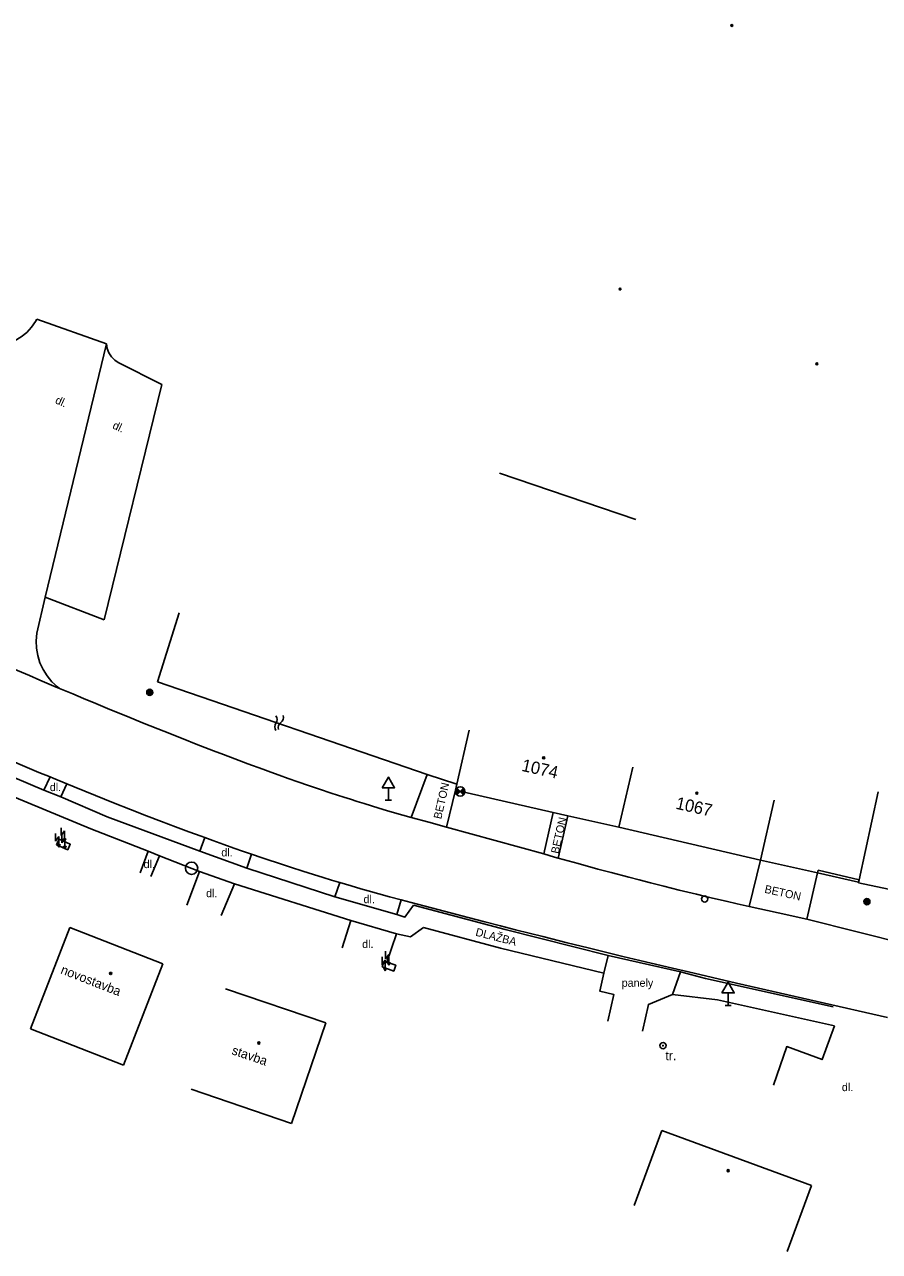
# Model space of a CAD drawing. Extents: x -540235 to -537963, y -1184915 to -1183660.
# Drawn here: x -538119.7 to -538050.3, y -1183997 to -1183897.3 of the extents above; entities that cross this region are included whole.
import ezdxf

# ---------------------------------------------------------------- set-up
doc = ezdxf.new("R2010")
doc.units = 0
for name, color, linetype in [('Vrstva 10', 7, 'Continuous'), ('Vrstva 11', 7, 'Continuous'), ('Vrstva 17', 7, 'Continuous'), ('Vrstva 20', 7, 'Continuous'), ('Vrstva 24', 7, 'Continuous'), ('Vrstva 25', 7, 'Continuous'), ('Vrstva 27', 7, 'Continuous'), ('Vrstva 28', 7, 'Continuous'), ('Vrstva 34', 7, 'Continuous'), ('Vrstva 39', 7, 'Continuous'), ('Vrstva 40', 7, 'Continuous'), ('Vrstva 41', 7, 'Continuous'), ('Vrstva 42', 7, 'Continuous'), ('Vrstva 47', 7, 'Continuous'), ('Vrstva 5', 7, 'Continuous'), ('Vrstva 7', 7, 'Continuous'), ('Vrstva 8', 7, 'Continuous')]:
    doc.layers.add(name, color=color, linetype=linetype)

msp = doc.modelspace()

# ---------------------------------------------------------------- linework, layer by layer
at = {"layer": 'Vrstva 10'}
for p, q in [((-538094.79, -1183959.736), (-538095.751, -1183959.417)), ((-538112.464, -1183960.529), (-538111.086, -1183961.074)), ((-538081.475, -1183963.59), (-538085.42, -1183962.5)), ((-538091.802, -1183967.666), (-538090.927, -1183967.911)), ((-538082.301, -1183970.194), (-538081.028, -1183970.522)), ((-538037.3, -1183974.7), (-538056.16, -1183969.97)), ((-538072.413, -1183972.672), (-538071.097, -1183972.991)), ((-538072.3, -1183972.91), (-538072.64, -1183974.37)), ((-538066.42, -1183974.26), (-538067.06, -1183976.08)), ((-538061.87, -1183975.16), (-538055.33, -1183976.652)), ((-538055.33, -1183976.652), (-538049.607, -1183977.953))]:
    msp.add_line(p, q, dxfattribs=at)
for points in [[(-538112.781, -1183952.939), (-538113.923, -1183952.469), (-538114.92, -1183952.054), (-538115.792, -1183951.69), (-538116.856, -1183951.241), (-538117.316, -1183951.047), (-538118.457, -1183950.561), (-538119.311, -1183950.194), (-538120.592, -1183949.64), (-538121.87, -1183949.08)], [(-538104.353, -1183956.303), (-538105.763, -1183955.757), (-538106.819, -1183955.342), (-538108.401, -1183954.714), (-538109.98, -1183954.08), (-538111.475, -1183953.474), (-538112.781, -1183952.939)], [(-538095.751, -1183959.417), (-538096.65, -1183959.113), (-538097.492, -1183958.822), (-538098.28, -1183958.547), (-538099.017, -1183958.285), (-538099.708, -1183958.037), (-538100.354, -1183957.803), (-538101.565, -1183957.357), (-538102.622, -1183956.962), (-538103.546, -1183956.612), (-538104.353, -1183956.303)], [(-538120.933, -1183957.045), (-538120.06, -1183957.413), (-538118.532, -1183958.053), (-538117.635, -1183958.425), (-538117.384, -1183958.529), (-538116.266, -1183958.988), (-538115.659, -1183959.237), (-538113.93, -1183959.94), (-538112.464, -1183960.529)], [(-538085.42, -1183962.5), (-538086.855, -1183962.105), (-538088.29, -1183961.71), (-538088.982, -1183961.517), (-538089.651, -1183961.326), (-538090.299, -1183961.137), (-538090.925, -1183960.951), (-538091.531, -1183960.769), (-538092.117, -1183960.589), (-538092.684, -1183960.413), (-538093.233, -1183960.24), (-538093.763, -1183960.07), (-538094.79, -1183959.736)], [(-538111.086, -1183961.074), (-538109.793, -1183961.578), (-538108.578, -1183962.045), (-538107.436, -1183962.477), (-538106.365, -1183962.877), (-538105.359, -1183963.247), (-538105.068, -1183963.353), (-538104.414, -1183963.59), (-538103.527, -1183963.908), (-538102.694, -1183964.202), (-538101.912, -1183964.475)], [(-538074.738, -1183965.466), (-538076.35, -1183965.02), (-538076.645, -1183964.936), (-538077.087, -1183964.807), (-538077.53, -1183964.68), (-538081.475, -1183963.59)], [(-538101.912, -1183964.475), (-538101.26, -1183964.7), (-538101.178, -1183964.728), (-538100.49, -1183964.963)], [(-538100.49, -1183964.963), (-538099.843, -1183965.18), (-538099.236, -1183965.382), (-538098.097, -1183965.755), (-538097.097, -1183966.076), (-538096.222, -1183966.352), (-538095.454, -1183966.589), (-538094.782, -1183966.794), (-538094.193, -1183966.971), (-538094.082, -1183967.004), (-538093.16, -1183967.276), (-538092.385, -1183967.501), (-538091.802, -1183967.666)], [(-538065.132, -1183967.947), (-538066.54, -1183967.605), (-538067.771, -1183967.299), (-538068.846, -1183967.027), (-538069.787, -1183966.785), (-538070.609, -1183966.572), (-538072.047, -1183966.193), (-538073.124, -1183965.904), (-538074.738, -1183965.466)], [(-538090.927, -1183967.911), (-538090.05, -1183968.15), (-538089.098, -1183968.406), (-538088.295, -1183968.621), (-538086.65, -1183969.059), (-538085.107, -1183969.465), (-538083.659, -1183969.843), (-538082.301, -1183970.194)], [(-538056.16, -1183969.97), (-538058.495, -1183969.455), (-538060.83, -1183968.94), (-538061.806, -1183968.722), (-538062.721, -1183968.514), (-538063.578, -1183968.315), (-538064.38, -1183968.127), (-538065.132, -1183967.947)], [(-538081.028, -1183970.522), (-538079.834, -1183970.826), (-538077.594, -1183971.392), (-538075.633, -1183971.881), (-538073.916, -1183972.305), (-538072.413, -1183972.672)], [(-538071.097, -1183972.991), (-538068.793, -1183973.544), (-538067.064, -1183973.954), (-538065.766, -1183974.258), (-538063.819, -1183974.712), (-538061.87, -1183975.16)], [(-538072.64, -1183974.37), (-538072.97, -1183975.83), (-538071.83, -1183976.1), (-538072.32, -1183978.268)], [(-538067.06, -1183976.08), (-538069.02, -1183976.9), (-538069.508, -1183979.057)]]:
    msp.add_lwpolyline(points, dxfattribs=at)
at = {"layer": 'Vrstva 11'}
for p, q in [((-538113.05, -1183923.26), (-538118.71, -1183921.25)), ((-538118.02, -1183943.82), (-538113.05, -1183923.26)), ((-538108.56, -1183926.57), (-538112.09, -1183924.78)), ((-538113.23, -1183945.67), (-538108.56, -1183926.57)), ((-538118.7, -1183946.76), (-538118.02, -1183943.82)), ((-538118.02, -1183943.82), (-538113.23, -1183945.67)), ((-538124.61, -1183956.73), (-538118.14, -1183959.51)), ((-538114.31, -1183962.64), (-538124.69, -1183958.34)), ((-538118.14, -1183959.51), (-538117.635, -1183958.425)), ((-538087, -1183958.23), (-538088.29, -1183961.71)), ((-538116.76, -1183960.05), (-538118.14, -1183959.51)), ((-538116.76, -1183960.05), (-538116.266, -1183958.988)), ((-538084.7, -1183959.51), (-538085.42, -1183962.5)), ((-538116.76, -1183960.05), (-538113, -1183961.67)), ((-538113, -1183961.67), (-538105.47, -1183964.46)), ((-538076.767, -1183961.304), (-538077.53, -1183964.68)), ((-538075.571, -1183961.574), (-538076.35, -1183965.02)), ((-538109.67, -1183964.45), (-538114.31, -1183962.64)), ((-538105.47, -1183964.46), (-538105.068, -1183963.353)), ((-538109.67, -1183964.45), (-538110.31, -1183966.2)), ((-538109.67, -1183964.45), (-538108.73, -1183964.83)), ((-538108.73, -1183964.83), (-538109.44, -1183966.51)), ((-538105.48, -1183966.11), (-538108.73, -1183964.83)), ((-538101.65, -1183965.83), (-538105.47, -1183964.46)), ((-538101.65, -1183965.83), (-538101.26, -1183964.7)), ((-538094.5, -1183968.16), (-538101.65, -1183965.83)), ((-538059.93, -1183965.17), (-538060.83, -1183968.94)), ((-538106.53, -1183968.84), (-538105.48, -1183966.11)), ((-538105.48, -1183966.11), (-538102.65, -1183967.1)), ((-538055.29, -1183966.2), (-538056.16, -1183969.97)), ((-538102.65, -1183967.1), (-538103.73, -1183969.68)), ((-538093.2, -1183970.08), (-538102.65, -1183967.1)), ((-538094.082, -1183967.004), (-538094.5, -1183968.16)), ((-538094.5, -1183968.16), (-538089.47, -1183969.6)), ((-538089.47, -1183969.6), (-538089.098, -1183968.406)), ((-538080.65, -1183970.8), (-538088.1, -1183968.83)), ((-538093.91, -1183972.31), (-538093.2, -1183970.08)), ((-538093.2, -1183970.08), (-538089.48, -1183971.16)), ((-538081.04, -1183972.32), (-538087.29, -1183970.64)), ((-538072.3, -1183972.91), (-538080.65, -1183970.8)), ((-538089.48, -1183971.16), (-538090.29, -1183973.54)), ((-538072.64, -1183974.37), (-538081.04, -1183972.32)), ((-538072.3, -1183972.91), (-538066.42, -1183974.26)), ((-538064.39, -1183974.78), (-538066.42, -1183974.26)), ((-538054.01, -1183977.1), (-538064.39, -1183974.78)), ((-538063.41, -1183976.53), (-538067.06, -1183976.08)), ((-538053.92, -1183978.64), (-538063.41, -1183976.53))]:
    msp.add_line(p, q, dxfattribs=at)
for points in [[(-538123.24, -1183923.34), (-538122.675, -1183923.427), (-538122.103, -1183923.435), (-538121.536, -1183923.363), (-538120.984, -1183923.213), (-538120.459, -1183922.987), (-538119.97, -1183922.69), (-538119.528, -1183922.328), (-538119.14, -1183921.908), (-538118.815, -1183921.438), (-538118.71, -1183921.25)], [(-538113.05, -1183923.26), (-538112.992, -1183923.637), (-538112.856, -1183923.994), (-538112.649, -1183924.315), (-538112.38, -1183924.586), (-538112.09, -1183924.78)], [(-538118.7, -1183946.76), (-538118.756, -1183947.367), (-538118.733, -1183947.975), (-538118.63, -1183948.576), (-538118.449, -1183949.158), (-538118.194, -1183949.711), (-538117.868, -1183950.226), (-538117.478, -1183950.694), (-538117.03, -1183951.107), (-538116.856, -1183951.241)], [(-538088.1, -1183968.83), (-538088.8, -1183969.81), (-538089.47, -1183969.6)], [(-538087.29, -1183970.64), (-538088.35, -1183971.41), (-538089.48, -1183971.16)], [(-538053.92, -1183978.64), (-538054.92, -1183981.38), (-538057.79, -1183980.32), (-538058.87, -1183983.44)]]:
    msp.add_lwpolyline(points, dxfattribs=at)
at = {"layer": 'Vrstva 17'}
for p, q in [((-538084.684, -1183959.621), (-538084.487, -1183959.423)), ((-538084.681, -1183959.547), (-538084.522, -1183959.388)), ((-538084.676, -1183959.683), (-538084.451, -1183959.459)), ((-538084.659, -1183959.737), (-538084.416, -1183959.494)), ((-538084.653, -1183959.448), (-538084.557, -1183959.353)), ((-538084.636, -1183959.785), (-538084.381, -1183959.529)), ((-538084.608, -1183959.827), (-538084.345, -1183959.565)), ((-538084.575, -1183959.865), (-538084.045, -1183959.335)), ((-538084.575, -1183959.335), (-538084.045, -1183959.865)), ((-538084.275, -1183959.635), (-538084.012, -1183959.373)), ((-538084.239, -1183959.671), (-538083.984, -1183959.415)), ((-538084.204, -1183959.706), (-538083.961, -1183959.463)), ((-538084.169, -1183959.741), (-538083.944, -1183959.517)), ((-538084.133, -1183959.777), (-538083.936, -1183959.579)), ((-538084.098, -1183959.812), (-538083.939, -1183959.653)), ((-538084.063, -1183959.847), (-538083.967, -1183959.752))]:
    msp.add_line(p, q, dxfattribs=at)
msp.add_circle((-538084.31, -1183959.6), 0.375, dxfattribs=at)
at = {"layer": 'Vrstva 20'}
for centre, radius in [((-538062.25, -1183897.41), 0.075), ((-538062.25, -1183897.41), 0.0204), ((-538071.33, -1183918.81), 0.075), ((-538071.33, -1183918.81), 0.0204), ((-538055.34, -1183924.89), 0.075), ((-538055.34, -1183924.89), 0.0204)]:
    msp.add_circle(centre, radius, dxfattribs=at)
at = {"layer": 'Vrstva 24'}
for p, q in [((-538116.72, -1183962.544), (-538116.72, -1183963.171)), ((-538116.72, -1183963.171), (-538116.47, -1183962.795)), ((-538116.47, -1183962.795), (-538116.47, -1183963.67)), ((-538117.18, -1183963.004), (-538117.18, -1183963.631)), ((-538117.18, -1183963.631), (-538116.93, -1183963.255)), ((-538117.039, -1183963.885), (-538116.93, -1183964.13)), ((-538116.93, -1183963.255), (-538116.93, -1183964.13)), ((-538116.93, -1183964.13), (-538116.819, -1183963.885)), ((-538116.67, -1183963.144), (-538116.67, -1183963.771)), ((-538116.67, -1183963.771), (-538116.42, -1183963.395)), ((-538116.579, -1183963.425), (-538116.47, -1183963.67)), ((-538116.47, -1183963.67), (-538116.359, -1183963.425)), ((-538116.42, -1183963.395), (-538116.42, -1183964.27)), ((-538116.529, -1183964.025), (-538116.42, -1183964.27)), ((-538116.42, -1183964.27), (-538116.309, -1183964.025)), ((-538090.37, -1183972.584), (-538090.37, -1183973.211)), ((-538090.37, -1183973.211), (-538090.12, -1183972.835)), ((-538090.12, -1183972.835), (-538090.12, -1183973.71)), ((-538090.65, -1183973.044), (-538090.65, -1183973.671)), ((-538090.65, -1183973.671), (-538090.4, -1183973.295)), ((-538090.4, -1183973.295), (-538090.4, -1183974.17)), ((-538090.229, -1183973.465), (-538090.12, -1183973.71)), ((-538090.12, -1183973.71), (-538090.009, -1183973.465)), ((-538090.509, -1183973.925), (-538090.4, -1183974.17)), ((-538090.4, -1183974.17), (-538090.289, -1183973.925))]:
    msp.add_line(p, q, dxfattribs=at)
for points in [[(-538117.109, -1183963.932), (-538116.197, -1183964.343), (-538115.991, -1183963.888), (-538116.903, -1183963.477)], [(-538090.655, -1183973.843), (-538089.716, -1183974.186), (-538089.545, -1183973.717), (-538090.484, -1183973.374)]]:
    msp.add_lwpolyline(points, close=True, dxfattribs=at)
for centre, start, end in [((-538099.68, -1183953.7603), 323.130103, 36.869897), ((-538099.1659, -1183953.5891), 304.1631, 17.902894), ((-538098.88, -1183954.3603), 143.130103, 216.869897), ((-538098.6043, -1183954.4166), 124.1631, 197.902894)]:
    msp.add_arc(centre, 0.5, start, end, dxfattribs=at)
at = {"layer": 'Vrstva 25'}
for centre, radius in [((-538109.53, -1183951.56), 0.25), ((-538109.53, -1183951.56), 0.2), ((-538109.53, -1183951.56), 0.15), ((-538109.53, -1183951.56), 0.1), ((-538109.53, -1183951.56), 0.05), ((-538051.28, -1183968.55), 0.25), ((-538051.28, -1183968.55), 0.2), ((-538051.28, -1183968.55), 0.15), ((-538051.28, -1183968.55), 0.1), ((-538051.28, -1183968.55), 0.05), ((-538067.84, -1183980.24), 0.25), ((-538067.84, -1183980.24), 0.0303)]:
    msp.add_circle(centre, radius, dxfattribs=at)
at = {"layer": 'Vrstva 27'}
msp.add_circle((-538106.13, -1183965.84), 0.5, dxfattribs=at)
at = {"layer": 'Vrstva 28'}
msp.add_circle((-538064.45, -1183968.33), 0.25, dxfattribs=at)
at = {"layer": 'Vrstva 34'}
for p, q in [((-538090.15, -1183959.302), (-538090.15, -1183960.32)), ((-538090.4, -1183960.32), (-538089.9, -1183960.32)), ((-538062.55, -1183975.964), (-538062.55, -1183976.98)), ((-538062.8, -1183976.98), (-538062.3, -1183976.98))]:
    msp.add_line(p, q, dxfattribs=at)
for points in [[(-538090.65, -1183959.302), (-538089.65, -1183959.302), (-538090.15, -1183958.436)], [(-538063.05, -1183975.964), (-538062.05, -1183975.964), (-538062.55, -1183975.096)]]:
    msp.add_lwpolyline(points, close=True, dxfattribs=at)
at = {"layer": 'Vrstva 39'}
for centre, radius in [((-538077.528, -1183956.876), 0.09), ((-538077.528, -1183956.876), 0.0398), ((-538065.09, -1183959.744), 0.09), ((-538065.09, -1183959.744), 0.0398), ((-538112.707, -1183974.38), 0.09), ((-538112.707, -1183974.38), 0.0398), ((-538100.675, -1183980.034), 0.09), ((-538100.675, -1183980.034), 0.0398), ((-538062.543, -1183990.399), 0.09), ((-538062.543, -1183990.399), 0.0398)]:
    msp.add_circle(centre, radius, dxfattribs=at)
at = {"layer": 'Vrstva 5'}
for p, q in [((-538083.597, -1183954.633), (-538084.589, -1183959.022)), ((-538070.303, -1183957.639), (-538071.43, -1183962.51)), ((-538084.589, -1183959.022), (-538084.7, -1183959.51)), ((-538076.767, -1183961.304), (-538084.7, -1183959.51)), ((-538058.803, -1183960.299), (-538059.93, -1183965.17)), ((-538075.571, -1183961.574), (-538076.767, -1183961.304)), ((-538071.43, -1183962.51), (-538075.571, -1183961.574)), ((-538059.93, -1183965.17), (-538071.43, -1183962.51)), ((-538051.96, -1183967.02), (-538034.21, -1183970.84)), ((-538119.23, -1183978.87), (-538116.03, -1183970.66)), ((-538116.03, -1183970.66), (-538108.46, -1183973.61)), ((-538108.46, -1183973.61), (-538111.66, -1183981.82)), ((-538103.386, -1183975.631), (-538095.24, -1183978.4)), ((-538095.24, -1183978.4), (-538098.01, -1183986.55)), ((-538111.66, -1183981.82), (-538119.23, -1183978.87)), ((-538098.01, -1183986.55), (-538106.156, -1183983.781)), ((-538070.175, -1183993.214), (-538067.93, -1183987.13)), ((-538067.93, -1183987.13), (-538055.79, -1183991.61)), ((-538055.79, -1183991.61), (-538057.762, -1183996.953))]:
    msp.add_line(p, q, dxfattribs=at)
msp.add_lwpolyline([(-538050.372, -1183959.641), (-538051.908, -1183966.778), (-538051.95, -1183966.973), (-538051.96, -1183967.02)], dxfattribs=at)
at = {"layer": 'Vrstva 7'}
for p, q in [((-538081.113, -1183933.757), (-538070.045, -1183937.527)), ((-538108.91, -1183950.7), (-538107.14, -1183945.107)), ((-538087, -1183958.23), (-538108.91, -1183950.7)), ((-538055.29, -1183966.2), (-538055.245, -1183966.005)), ((-538055.29, -1183966.2), (-538051.95, -1183966.973)), ((-538051.908, -1183966.778), (-538055.245, -1183966.005))]:
    msp.add_line(p, q, dxfattribs=at)
at = {"layer": 'Vrstva 8'}
for p, q in [((-538087, -1183958.23), (-538084.589, -1183959.022)), ((-538059.93, -1183965.17), (-538055.29, -1183966.2))]:
    msp.add_line(p, q, dxfattribs=at)

# ---------------------------------------------------------------- texts
at = {"layer": 'Vrstva 40'}
for s, rotation, p in [('dl.', 335.544222, (-538117.27, -1183928.056)), ('dl.', 335.544222, (-538112.61, -1183930.106)), ('BETON', 77.256175, (-538085.855, -1183961.888)), ('BETON', 77.261861, (-538076.322, -1183964.7)), ('BETON', 347.571725, (-538059.634, -1183967.819)), ('DLAŽBA', 345.683186, (-538083.115, -1183971.305))]:
    msp.add_text(s, height=0.65, rotation=rotation, dxfattribs=at).set_placement(p)
for s, p in [('dl.', (-538117.649, -1183959.575)), ('dl.', (-538103.719, -1183964.878)), ('dl.', (-538110.031, -1183965.828)), ('dl.', (-538104.955, -1183968.19)), ('dl.', (-538092.166, -1183968.675)), ('dl.', (-538092.276, -1183972.317)), ('panely', (-538071.194, -1183975.464)), ('dl.', (-538053.309, -1183983.937))]:
    msp.add_text(s, height=0.65, dxfattribs=at).set_placement(p)
at = {"layer": 'Vrstva 41'}
for s, rotation, p in [('novostavba', 338.709322, (-538116.83, -1183974.363)), ('stavba', 341.226003, (-538102.933, -1183980.925))]:
    msp.add_text(s, height=0.75, rotation=rotation, dxfattribs=at).set_placement(p)
at = {"layer": 'Vrstva 42'}
msp.add_text('tr.', height=0.75, dxfattribs=at).set_placement((-538067.646, -1183981.425))
at = {"layer": 'Vrstva 47'}
for s, p in [('1074', (-538079.387, -1183957.925)), ('1067', (-538066.868, -1183961.001))]:
    msp.add_text(s, height=1, rotation=347.4712, dxfattribs=at).set_placement(p)

doc.saveas('drawing.dxf')
